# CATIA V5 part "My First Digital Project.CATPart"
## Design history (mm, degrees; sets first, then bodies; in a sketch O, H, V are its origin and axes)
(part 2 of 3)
Set37 "UDF Geometry"
  Point54 "B-L": (25.4 {= UdfFeature14.FrameThickness}, 0, 25.4 {= UdfFeature14.FrameThickness}), relative to vertex [YZ plane of UdfFeature14 | ZX plane of UdfFeature14 | XY plane of UdfFeature14], in 
  Point55 "B": (507.9492 {= `UdfFeature14.Panel Width` /2}, 0, 25.4 {= UdfFeature14.FrameThickness}), relative to vertex [YZ plane of UdfFeature14 | ZX plane of UdfFeature14 | XY plane of UdfFeature14], in 
  Point56 "B-R": (990.4984 {= `UdfFeature14.Panel Width` -UdfFeature14.FrameThickness}, 0, 25.4 {= UdfFeature14.FrameThickness}), relative to vertex [YZ plane of UdfFeature14 | ZX plane of UdfFeature14 | XY plane of UdfFeature14], in 
  Point57 "R": (990.4984 {= Point56.X}, 0, 1143 {= `UdfFeature14.Panel Height` /2}), relative to vertex [YZ plane of UdfFeature14 | ZX plane of UdfFeature14 | XY plane of UdfFeature14], in 
  Point58 "T-R": (990.4984 {= Point56.X}, 0, 2260.6 {= `UdfFeature14.Panel Height` -UdfFeature14.FrameThickness}), relative to vertex [YZ plane of UdfFeature14 | ZX plane of UdfFeature14 | XY plane of UdfFeature14], in 
  Point59 "T": (507.9492 {= Point55.X}, 0, 2260.6 {= Point58.Z}), relative to vertex [YZ plane of UdfFeature14 | ZX plane of UdfFeature14 | XY plane of UdfFeature14], in 
  Point60 "T-L": (25.4 {= Point54.X}, 0, 2260.6 {= Point58.Z}), relative to vertex [YZ plane of UdfFeature14 | ZX plane of UdfFeature14 | XY plane of UdfFeature14], in 
  Point61 "L": (25.4 {= Point54.X}, 0, 1143 {= Point57.Z}), relative to vertex [YZ plane of UdfFeature14 | ZX plane of UdfFeature14 | XY plane of UdfFeature14], in 
  Point62 "C": (507.9492 {= `UdfFeature14.Panel Width` /2}, 0, 1143 {= `UdfFeature14.Panel Height` /2}), relative to vertex [YZ plane of UdfFeature14 | ZX plane of UdfFeature14 | XY plane of UdfFeature14], in 
  Point63 "B2": (0, 0, 76.2), relative to Point55, in 
  Point64 "T2": (0, 0, -76.2), relative to Point59, in 
  Point65 "L2": (76.2, 0, 0), relative to Point61, in 
  Point66 "R2": (-76.2, 0, 0), relative to Point57, in 
  Point67 "L3": (-253.9746 {= -`UdfFeature14.Panel Width` /4}, 0, 0), relative to Point62, in 
  Point68 "R3": (253.9746 {= -Point67.X}, 0, 0), relative to Point62, in 
  Point69 "T3": (0, 0, 571.5 {= `UdfFeature14.Panel Height` /4}), relative to Point62, in 
  Point70 "B3": (0, 0, -571.5 {= - Point69.Z}), relative to Point62, in 
  LineCorner13 "Left": Elements (Point60; Point57; Point54)
  LineCorner14 "Right": Elements (Point58; Point61; Point56)
  LineCorner15 "Top": Elements (Point60; Point55; Point58)
  LineCorner16 "Bottom": Elements (Point54; Point59; Point56)
  Join6 "Left and Bottom": Elements (LineCorner13; LineCorner16)
  Join7 "Right and Bottom": Elements (LineCorner14; LineCorner16)
  LineCorner17 "Pivot H Top": Elements (Point65; Point61; Point59; Point57; Point66)
  LineCorner18 "Pivot H Bottom": Elements (Point61; Point55; Point57)
  Join8 "Pivot H": Elements (LineCorner17; LineCorner18)
  LineCorner19 "Pivot V Left": Elements (Point64; Point59; Point61; Point55; Point63)
  LineCorner20 "Pivot V Right": Elements (Point59; Point57; Point55)
  Join9 "Pivot V": Elements (LineCorner19; LineCorner20)
  Line28 "Sliding H": type PtPt, FirstPoint Point67, SecondPoint Point68
  Line29 "Sliding V": type PtPt, FirstPoint Point69, SecondPoint Point70
  Point71: (25.4 {= UdfFeature14.FrameThickness}, 0, 0), relative to Point54, in 
  Point72: (-25.4 {= -UdfFeature14.FrameThickness}, 0, 25.4 {= UdfFeature14.FrameThickness}), relative to Point56, in 
  Point73: (25.4 {= UdfFeature14.FrameThickness}, 0, -25.4 {= -UdfFeature14.FrameThickness}), relative to Point60, in 
  Point74: (-25.4 {= -UdfFeature14.FrameThickness}, 0, 0), relative to Point58, in 
  Point75: (0, 0, -25.4 {= -UdfFeature14.FrameThickness}), relative to Point58, in 
  Point76: (0, 0, 25.4 {= UdfFeature14.FrameThickness}), relative to Point54, in 
  LineCorner21 "Removable-1": Elements (Point60; Point74; Point72; Point76)
  LineCorner22 "Removable-2": Elements (Point73; Point75; Point56; Point71)
  Line30 "Removable-3": type PtPt, FirstPoint Point75, SecondPoint Point71
  Join10 "Removable": Elements (LineCorner21; LineCorner22; Line30)
  LineCorner23 "Fixed": Elements (Point60; Point58; Point56; Point54)
  DatumCurve2 "OperationSymbol"
Body24 "Opening Volume Body"
  GTCArcGeoOpnVolume5 "Opening Volume"
Set38 "IFC Triple Panel Vertical"
  Set39 "Construction Geometry"
    UdfFeature15 "Insertion Axis": UdfInputSpec1 {plane2lines}, UdfInputSpec3 Project11, UdfInputSpec4 Project12, UdfInputSpec5 Project13, UdfComponents Set44, UdfOutputs AxisSystem25
    AxisSystem20 "Insertion Axis Clone": origin (6685.672, 13208.4683, 742.95), X (-0.3932, -0.9195, 0), Y (0.9195, -0.3932, 0), Z (0, 0, 1)
    AxisSystem21 "Lining Axis": origin (6720.7034, 13193.4881, 742.95), X (-0.3932, -0.9195, 0), Y (0.9195, -0.3932, 0), Z (0, 0, 1)
    UdfFeature16 "Middle": UdfInputSpec1 {pointcoord X 0, Y 0, Z 0, RefAxis AxisSystem21}, UdfInputSpec2 {pointcoord X 1238.25 {= `UdfFeature16.Window Width` /2}, Y 0, Z 0, RefAxis AxisSystem21}, UdfInputSpec3 {pointcoord X 2476.5 {= `UdfFeature16.Window Width`}, Y 0, Z 0, RefAxis AxisSystem21}, UdfComponents Set45, UdfOutputs Point78
  Set40 "Window Panel - Left"
    AxisSystem22 "Panel Axis Left": origin (6684.0204, 13188.4559, 762), X (-0.3932, -0.9195, 0), Y (0.9195, -0.3932, 0), Z (0, 0, 1)
    Body25 "Panel"
      UdfFeature17 "IFC Window Panel": UdfInputSpec10 edge [ZX plane of AxisSystem22 | YZ plane of AxisSystem22], UdfInputSpec1 {pointcoord X 0 {= `External.Rotate Axis Offset`}, Y 0, Z 0, RefPoint vertex [YZ plane of AxisSystem22 | ZX plane of AxisSystem22 | XY plane of AxisSystem22], RefAxis AxisSystem22}, UdfInputSpec3 edge [ZX plane of AxisSystem22 | YZ plane of AxisSystem22], UdfInputSpec4 {pointcoord X 0, Y 0, Z 0 {= `External.Rotate Axis Offset`}, RefPoint vertex [YZ plane of AxisSystem22 | ZX plane of AxisSystem22 | XY plane of AxisSystem22], RefAxis AxisSystem22}, UdfComponents a sketch, UdfInputSpec6 edge [XY plane of AxisSystem22 | ZX plane of AxisSystem22], UdfInputSpec7 {pointcoord X 0 {= `External.X Translate`}, Y 0, Z 0 {= `External.Z Translate`}, RefPoint vertex [YZ plane of AxisSystem22 | ZX plane of AxisSystem22 | XY plane of AxisSystem22], RefAxis AxisSystem22}, UdfInputSpec9 edge [XY plane of AxisSystem22 | ZX plane of AxisSystem22], UdfActivity true, OperationType "FixedCasement", Open Ratio 10
  Set41 "Window Panel - Middle"
    AxisSystem23 "Panel Axis Middle": origin (6357.815, 12425.624, 762), X (-0.3932, -0.9195, 0), Y (0.9195, -0.3932, 0), Z (0, 0, 1)
    Body26 "Panel"
      UdfFeature18 "IFC Window Panel": UdfInputSpec10 edge [ZX plane of AxisSystem23 | YZ plane of AxisSystem23], UdfInputSpec1 {pointcoord X 0 {= `External.Rotate Axis Offset`}, Y 0, Z 0, RefPoint vertex [YZ plane of AxisSystem23 | ZX plane of AxisSystem23 | XY plane of AxisSystem23], RefAxis AxisSystem23}, UdfInputSpec3 edge [ZX plane of AxisSystem23 | YZ plane of AxisSystem23], UdfInputSpec4 {pointcoord X 0, Y 0, Z 0 {= `External.Rotate Axis Offset`}, RefPoint vertex [YZ plane of AxisSystem23 | ZX plane of AxisSystem23 | XY plane of AxisSystem23], RefAxis AxisSystem23}, UdfComponents a sketch, UdfInputSpec6 edge [XY plane of AxisSystem23 | ZX plane of AxisSystem23], UdfInputSpec7 {pointcoord X 0 {= `External.X Translate`}, Y 0, Z 0 {= `External.Z Translate`}, RefPoint vertex [YZ plane of AxisSystem23 | ZX plane of AxisSystem23 | XY plane of AxisSystem23], RefAxis AxisSystem23}, UdfInputSpec9 edge [XY plane of AxisSystem23 | ZX plane of AxisSystem23], OperationType "FixedCasement", Open Ratio 10
  Set42 "Window Panel - Right"
    AxisSystem24 "Panel Axis Right": origin (6031.6095, 11662.7921, 762), X (-0.3932, -0.9195, 0), Y (0.9195, -0.3932, 0), Z (0, 0, 1)
    Body27 "Panel"
      UdfFeature19 "IFC Window Panel": UdfInputSpec10 edge [ZX plane of AxisSystem24 | YZ plane of AxisSystem24], UdfInputSpec1 {pointcoord X 0 {= `External.Rotate Axis Offset`}, Y 0, Z 0, RefPoint vertex [YZ plane of AxisSystem24 | ZX plane of AxisSystem24 | XY plane of AxisSystem24], RefAxis AxisSystem24}, UdfInputSpec3 edge [ZX plane of AxisSystem24 | YZ plane of AxisSystem24], UdfInputSpec4 {pointcoord X 0, Y 0, Z 0 {= `External.Rotate Axis Offset`}, RefPoint vertex [YZ plane of AxisSystem24 | ZX plane of AxisSystem24 | XY plane of AxisSystem24], RefAxis AxisSystem24}, UdfComponents a sketch, UdfInputSpec6 edge [XY plane of AxisSystem24 | ZX plane of AxisSystem24], UdfInputSpec7 {pointcoord X 0 {= `External.X Translate`}, Y 0, Z 0 {= `External.Z Translate`}, RefPoint vertex [YZ plane of AxisSystem24 | ZX plane of AxisSystem24 | XY plane of AxisSystem24], RefAxis AxisSystem24}, UdfInputSpec9 edge [XY plane of AxisSystem24 | ZX plane of AxisSystem24], OperationType "FixedCasement", Open Ratio 10
  Set43 "Window Lining"
    Sketch14 "Opening Contour" on edge [XY plane of AxisSystem21 | ZX plane of AxisSystem21], origin (6720.7034, 13193.4881, 742.95), H (-0.3932, -0.9195, 0), V (0, 0, 1)
      line L1 (0, 0) -> (2476.5, 0)
      line L2 (2476.5, 0) -> (2476.5, 1866.9)
      line L3 (2476.5, 1866.9) -> (0, 1866.9)
      line L4 (0, 1866.9) -> (0, 0)
      length L4 = 1866.9
      length L3 = 2476.5
      horizontal: L1 H, L3 H
      vertical: L2 V, L4 V
    Body28 "Lining"
      Pad5: profile Sketch14, direction (-0.9195, 0.3932, 0), length 38.1, mirrored extent
      Pocket1: profile , through (limit type 3), opposite side through (limit type 3)
      Pocket2: profile , through (limit type 3), opposite side through (limit type 3)
      Pocket3: profile , through (limit type 3), opposite side through (limit type 3)
Set44 "Insertion Geometry"
  Plane11 "Construction Plane": type 2Lines
  Project11 "Insertion Point clone": Support Plane11
  Project12 "Insertion Line Clone": Support Plane11
  Project13 "Orientation Line Clone": Support Plane11
  Line31 "X Direction": type Normal, RefPoint Project11, RefSkin Plane11, Start 0, End 1
  AxisSystem25 "Insertion Axis": origin (6685.672, 13208.4683, 742.95), X (-0.3932, -0.9195, 0), Y (0.9195, -0.3932, 0), Z (0, 0, 1)
Set45 "UDF Geometry"
  Point77 "Left": (0, 0, 0), in AxisSystem21
  Point78 "Middle": (1238.25 {= `UdfFeature16.Window Width` /2}, 0, 0), in AxisSystem21
  Point79 "Right": (2476.5 {= `UdfFeature16.Window Width`}, 0, 0), in AxisSystem21
Set46 "UDF Geometry"
  Line32 "V Rotation Axis": type PtDir, RefPoint {point type Coord, X 0 {= `External.Rotate Axis Offset`}, Y 0, Z 0, RefPoint vertex [YZ plane of AxisSystem22 | ZX plane of AxisSystem22 | XY plane of AxisSystem22], RefAxis AxisSystem22}, Direction edge [ZX plane of AxisSystem22 | YZ plane of AxisSystem22], Start 0, End 304.8
  Line33 "H Rotation Axis": type PtDir, RefPoint {point type Coord, X 0, Y 0, Z 0 {= `External.Rotate Axis Offset`}, RefPoint vertex [YZ plane of AxisSystem22 | ZX plane of AxisSystem22 | XY plane of AxisSystem22], RefAxis AxisSystem22}, Direction edge [XY plane of AxisSystem22 | ZX plane of AxisSystem22], Start 0, End 304.8
  Point80 "Translate Point": (0 {= `External.X Translate`}, 0, 0 {= `External.Z Translate`}), relative to vertex [YZ plane of AxisSystem22 | ZX plane of AxisSystem22 | XY plane of AxisSystem22], in AxisSystem22
  Line34 "Trans X Axis": type PtDir, RefPoint Point80, Direction edge [XY plane of AxisSystem22 | ZX plane of AxisSystem22], Start 0, End 304.8
  Line35 "Trans ZAxis": type PtDir, RefPoint Point80, Direction edge [ZX plane of AxisSystem22 | YZ plane of AxisSystem22], Start 0, End 304.8
  Rotate9 "Rotate Horizontal Point": ToTransfor Point80, Axis Line33, Angle 0 {= `External.Open Angle`}
  Rotate10 "Rotate Horizontal Z Axis": ToTransfor Line35, Axis Line33, Angle 0 {= `External.Open Angle`}
  Rotate11 "Rotate Vertical Point": ToTransfor Point80, Axis Line32, Angle 0 {= `External.Open Angle`}
  Rotate12 "Rotate Vertical X Axis": ToTransfor Line34, Axis Line32, Angle 0 {= `External.Open Angle`}
  Line36 "X Direction": stored without definition
  Line37 "Z Direction": stored without definition
  Point81 "Origin": stored without definition
  Plane12: type Normal, Curve Line37, RefPoint Point81
  Line38 "Y Direction": type Angle, RefPoint Point81, Curve Line36, Support Plane12, Start 0, End 304.8, Angle 90
  AxisSystem26 "Window Open Axis": origin (6684.0204, 13188.4559, 762), X (-0.3932, -0.9195, 0), Y (0.9195, -0.3932, 0), Z (0, 0, 1)
Set47 "UDF Geometry"
  Point82 "B-L": (25.4 {= UdfFeature17.FrameThickness}, 0, 25.4 {= UdfFeature17.FrameThickness}), relative to vertex [YZ plane of UdfFeature17 | ZX plane of UdfFeature17 | XY plane of UdfFeature17], in 
  Point83 "B": (389.426 {= `UdfFeature17.Panel Width` /2}, 0, 25.4 {= UdfFeature17.FrameThickness}), relative to vertex [YZ plane of UdfFeature17 | ZX plane of UdfFeature17 | XY plane of UdfFeature17], in 
  Point84 "B-R": (753.4521 {= `UdfFeature17.Panel Width` -UdfFeature17.FrameThickness}, 0, 25.4 {= UdfFeature17.FrameThickness}), relative to vertex [YZ plane of UdfFeature17 | ZX plane of UdfFeature17 | XY plane of UdfFeature17], in 
  Point85 "R": (753.4521 {= Point84.X}, 0, 914.4 {= `UdfFeature17.Panel Height` /2}), relative to vertex [YZ plane of UdfFeature17 | ZX plane of UdfFeature17 | XY plane of UdfFeature17], in 
  Point86 "T-R": (753.4521 {= Point84.X}, 0, 1803.4 {= `UdfFeature17.Panel Height` -UdfFeature17.FrameThickness}), relative to vertex [YZ plane of UdfFeature17 | ZX plane of UdfFeature17 | XY plane of UdfFeature17], in 
  Point87 "T": (389.426 {= Point83.X}, 0, 1803.4 {= Point86.Z}), relative to vertex [YZ plane of UdfFeature17 | ZX plane of UdfFeature17 | XY plane of UdfFeature17], in 
  Point88 "T-L": (25.4 {= Point82.X}, 0, 1803.4 {= Point86.Z}), relative to vertex [YZ plane of UdfFeature17 | ZX plane of UdfFeature17 | XY plane of UdfFeature17], in 
  Point89 "L": (25.4 {= Point82.X}, 0, 914.4 {= Point85.Z}), relative to vertex [YZ plane of UdfFeature17 | ZX plane of UdfFeature17 | XY plane of UdfFeature17], in 
  Point90 "C": (389.426 {= `UdfFeature17.Panel Width` /2}, 0, 914.4 {= `UdfFeature17.Panel Height` /2}), relative to vertex [YZ plane of UdfFeature17 | ZX plane of UdfFeature17 | XY plane of UdfFeature17], in 
  Point91 "B2": (0, 0, 76.2), relative to Point83, in 
  Point92 "T2": (0, 0, -76.2), relative to Point87, in 
  Point93 "L2": (76.2, 0, 0), relative to Point89, in 
  Point94 "R2": (-76.2, 0, 0), relative to Point85, in 
  Point95 "L3": (-194.713 {= -`UdfFeature17.Panel Width` /4}, 0, 0), relative to Point90, in 
  Point96 "R3": (194.713 {= -Point95.X}, 0, 0), relative to Point90, in 
  Point97 "T3": (0, 0, 457.2 {= `UdfFeature17.Panel Height` /4}), relative to Point90, in 
  Point98 "B3": (0, 0, -457.2 {= - Point97.Z}), relative to Point90, in 
  LineCorner24 "Left": Elements (Point88; Point85; Point82)
  LineCorner25 "Right": Elements (Point86; Point89; Point84)
  LineCorner26 "Top": Elements (Point88; Point83; Point86)
  LineCorner27 "Bottom": Elements (Point82; Point87; Point84)
  Join11 "Left and Bottom": Elements (LineCorner24; LineCorner27)
  Join12 "Right and Bottom": Elements (LineCorner25; LineCorner27)
  LineCorner28 "Pivot H Top": Elements (Point93; Point89; Point87; Point85; Point94)
  LineCorner29 "Pivot H Bottom": Elements (Point89; Point83; Point85)
  Join13 "Pivot H": Elements (LineCorner28; LineCorner29)
  LineCorner30 "Pivot V Left": Elements (Point92; Point87; Point89; Point83; Point91)
  LineCorner31 "Pivot V Right": Elements (Point87; Point85; Point83)
  Join14 "Pivot V": Elements (LineCorner30; LineCorner31)
  Line39 "Sliding H": type PtPt, FirstPoint Point95, SecondPoint Point96
  Line40 "Sliding V": type PtPt, FirstPoint Point97, SecondPoint Point98
  Point99: (25.4 {= UdfFeature17.FrameThickness}, 0, 0), relative to Point82, in 
  Point100: (-25.4 {= -UdfFeature17.FrameThickness}, 0, 25.4 {= UdfFeature17.FrameThickness}), relative to Point84, in 
  Point101: (25.4 {= UdfFeature17.FrameThickness}, 0, -25.4 {= -UdfFeature17.FrameThickness}), relative to Point88, in 
  Point102: (-25.4 {= -UdfFeature17.FrameThickness}, 0, 0), relative to Point86, in 
  Point103: (0, 0, -25.4 {= -UdfFeature17.FrameThickness}), relative to Point86, in 
  Point104: (0, 0, 25.4 {= UdfFeature17.FrameThickness}), relative to Point82, in 
  LineCorner32 "Removable-1": Elements (Point88; Point102; Point100; Point104)
  LineCorner33 "Removable-2": Elements (Point101; Point103; Point84; Point99)
  Line41 "Removable-3": type PtPt, FirstPoint Point103, SecondPoint Point99
  Join15 "Removable": Elements (LineCorner32; LineCorner33; Line41)
  LineCorner34 "Fixed": Elements (Point88; Point86; Point84; Point82)
  DatumCurve3 "OperationSymbol"
Set48 "UDF Geometry"
  Line42 "V Rotation Axis": type PtDir, RefPoint {point type Coord, X 0 {= `External.Rotate Axis Offset`}, Y 0, Z 0, RefPoint vertex [YZ plane of AxisSystem23 | ZX plane of AxisSystem23 | XY plane of AxisSystem23], RefAxis AxisSystem23}, Direction edge [ZX plane of AxisSystem23 | YZ plane of AxisSystem23], Start 0, End 304.8
  Line43 "H Rotation Axis": type PtDir, RefPoint {point type Coord, X 0, Y 0, Z 0 {= `External.Rotate Axis Offset`}, RefPoint vertex [YZ plane of AxisSystem23 | ZX plane of AxisSystem23 | XY plane of AxisSystem23], RefAxis AxisSystem23}, Direction edge [XY plane of AxisSystem23 | ZX plane of AxisSystem23], Start 0, End 304.8
  Point105 "Translate Point": (0 {= `External.X Translate`}, 0, 0 {= `External.Z Translate`}), relative to vertex [YZ plane of AxisSystem23 | ZX plane of AxisSystem23 | XY plane of AxisSystem23], in AxisSystem23
  Line44 "Trans X Axis": type PtDir, RefPoint Point105, Direction edge [XY plane of AxisSystem23 | ZX plane of AxisSystem23], Start 0, End 304.8
  Line45 "Trans ZAxis": type PtDir, RefPoint Point105, Direction edge [ZX plane of AxisSystem23 | YZ plane of AxisSystem23], Start 0, End 304.8
  Rotate13 "Rotate Horizontal Point": ToTransfor Point105, Axis Line43, Angle 0 {= `External.Open Angle`}
  Rotate14 "Rotate Horizontal Z Axis": ToTransfor Line45, Axis Line43, Angle 0 {= `External.Open Angle`}
  Rotate15 "Rotate Vertical Point": ToTransfor Point105, Axis Line42, Angle 0 {= `External.Open Angle`}
  Rotate16 "Rotate Vertical X Axis": ToTransfor Line44, Axis Line42, Angle 0 {= `External.Open Angle`}
  Line46 "X Direction": stored without definition
  Line47 "Z Direction": stored without definition
  Point106 "Origin": stored without definition
  Plane13: type Normal, Curve Line47, RefPoint Point106
  Line48 "Y Direction": type Angle, RefPoint Point106, Curve Line46, Support Plane13, Start 0, End 304.8, Angle 90
  AxisSystem27 "Window Open Axis": origin (6357.815, 12425.624, 762), X (-0.3932, -0.9195, 0), Y (0.9195, -0.3932, 0), Z (0, 0, 1)
Set49 "UDF Geometry"
  Point107 "B-L": (25.4 {= UdfFeature18.FrameThickness}, 0, 25.4 {= UdfFeature18.FrameThickness}), relative to vertex [YZ plane of UdfFeature18 | ZX plane of UdfFeature18 | XY plane of UdfFeature18], in 
  Point108 "B": (389.426 {= `UdfFeature18.Panel Width` /2}, 0, 25.4 {= UdfFeature18.FrameThickness}), relative to vertex [YZ plane of UdfFeature18 | ZX plane of UdfFeature18 | XY plane of UdfFeature18], in 
  Point109 "B-R": (753.4521 {= `UdfFeature18.Panel Width` -UdfFeature18.FrameThickness}, 0, 25.4 {= UdfFeature18.FrameThickness}), relative to vertex [YZ plane of UdfFeature18 | ZX plane of UdfFeature18 | XY plane of UdfFeature18], in 
  Point110 "R": (753.4521 {= Point109.X}, 0, 914.4 {= `UdfFeature18.Panel Height` /2}), relative to vertex [YZ plane of UdfFeature18 | ZX plane of UdfFeature18 | XY plane of UdfFeature18], in 
  Point111 "T-R": (753.4521 {= Point109.X}, 0, 1803.4 {= `UdfFeature18.Panel Height` -UdfFeature18.FrameThickness}), relative to vertex [YZ plane of UdfFeature18 | ZX plane of UdfFeature18 | XY plane of UdfFeature18], in 
  Point112 "T": (389.426 {= Point108.X}, 0, 1803.4 {= Point111.Z}), relative to vertex [YZ plane of UdfFeature18 | ZX plane of UdfFeature18 | XY plane of UdfFeature18], in 
  Point113 "T-L": (25.4 {= Point107.X}, 0, 1803.4 {= Point111.Z}), relative to vertex [YZ plane of UdfFeature18 | ZX plane of UdfFeature18 | XY plane of UdfFeature18], in 
  Point114 "L": (25.4 {= Point107.X}, 0, 914.4 {= Point110.Z}), relative to vertex [YZ plane of UdfFeature18 | ZX plane of UdfFeature18 | XY plane of UdfFeature18], in 
  Point115 "C": (389.426 {= `UdfFeature18.Panel Width` /2}, 0, 914.4 {= `UdfFeature18.Panel Height` /2}), relative to vertex [YZ plane of UdfFeature18 | ZX plane of UdfFeature18 | XY plane of UdfFeature18], in 
  Point116 "B2": (0, 0, 76.2), relative to Point108, in 
  Point117 "T2": (0, 0, -76.2), relative to Point112, in 
  Point118 "L2": (76.2, 0, 0), relative to Point114, in 
  Point119 "R2": (-76.2, 0, 0), relative to Point110, in 
  Point120 "L3": (-194.713 {= -`UdfFeature18.Panel Width` /4}, 0, 0), relative to Point115, in 
  Point121 "R3": (194.713 {= -Point120.X}, 0, 0), relative to Point115, in 
  Point122 "T3": (0, 0, 457.2 {= `UdfFeature18.Panel Height` /4}), relative to Point115, in 
  Point123 "B3": (0, 0, -457.2 {= - Point122.Z}), relative to Point115, in 
  LineCorner35 "Left": Elements (Point113; Point110; Point107)
  LineCorner36 "Right": Elements (Point111; Point114; Point109)
  LineCorner37 "Top": Elements (Point113; Point108; Point111)
  LineCorner38 "Bottom": Elements (Point107; Point112; Point109)
  Join16 "Left and Bottom": Elements (LineCorner35; LineCorner38)
  Join17 "Right and Bottom": Elements (LineCorner36; LineCorner38)
  LineCorner39 "Pivot H Top": Elements (Point118; Point114; Point112; Point110; Point119)
  LineCorner40 "Pivot H Bottom": Elements (Point114; Point108; Point110)
  Join18 "Pivot H": Elements (LineCorner39; LineCorner40)
  LineCorner41 "Pivot V Left": Elements (Point117; Point112; Point114; Point108; Point116)
  LineCorner42 "Pivot V Right": Elements (Point112; Point110; Point108)
  Join19 "Pivot V": Elements (LineCorner41; LineCorner42)
  Line49 "Sliding H": type PtPt, FirstPoint Point120, SecondPoint Point121
  Line50 "Sliding V": type PtPt, FirstPoint Point122, SecondPoint Point123
  Point124: (25.4 {= UdfFeature18.FrameThickness}, 0, 0), relative to Point107, in 
  Point125: (-25.4 {= -UdfFeature18.FrameThickness}, 0, 25.4 {= UdfFeature18.FrameThickness}), relative to Point109, in 
  Point126: (25.4 {= UdfFeature18.FrameThickness}, 0, -25.4 {= -UdfFeature18.FrameThickness}), relative to Point113, in 
  Point127: (-25.4 {= -UdfFeature18.FrameThickness}, 0, 0), relative to Point111, in 
  Point128: (0, 0, -25.4 {= -UdfFeature18.FrameThickness}), relative to Point111, in 
  Point129: (0, 0, 25.4 {= UdfFeature18.FrameThickness}), relative to Point107, in 
  LineCorner43 "Removable-1": Elements (Point113; Point127; Point125; Point129)
  LineCorner44 "Removable-2": Elements (Point126; Point128; Point109; Point124)
  Line51 "Removable-3": type PtPt, FirstPoint Point128, SecondPoint Point124
  Join20 "Removable": Elements (LineCorner43; LineCorner44; Line51)
  LineCorner45 "Fixed": Elements (Point113; Point111; Point109; Point107)
  DatumCurve4 "OperationSymbol"
Set50 "UDF Geometry"
  Line52 "V Rotation Axis": type PtDir, RefPoint {point type Coord, X 0 {= `External.Rotate Axis Offset`}, Y 0, Z 0, RefPoint vertex [YZ plane of AxisSystem24 | ZX plane of AxisSystem24 | XY plane of AxisSystem24], RefAxis AxisSystem24}, Direction edge [ZX plane of AxisSystem24 | YZ plane of AxisSystem24], Start 0, End 304.8
  Line53 "H Rotation Axis": type PtDir, RefPoint {point type Coord, X 0, Y 0, Z 0 {= `External.Rotate Axis Offset`}, RefPoint vertex [YZ plane of AxisSystem24 | ZX plane of AxisSystem24 | XY plane of AxisSystem24], RefAxis AxisSystem24}, Direction edge [XY plane of AxisSystem24 | ZX plane of AxisSystem24], Start 0, End 304.8
  Point130 "Translate Point": (0 {= `External.X Translate`}, 0, 0 {= `External.Z Translate`}), relative to vertex [YZ plane of AxisSystem24 | ZX plane of AxisSystem24 | XY plane of AxisSystem24], in AxisSystem24
  Line54 "Trans X Axis": type PtDir, RefPoint Point130, Direction edge [XY plane of AxisSystem24 | ZX plane of AxisSystem24], Start 0, End 304.8
  Line55 "Trans ZAxis": type PtDir, RefPoint Point130, Direction edge [ZX plane of AxisSystem24 | YZ plane of AxisSystem24], Start 0, End 304.8
  Rotate17 "Rotate Horizontal Point": ToTransfor Point130, Axis Line53, Angle 0 {= `External.Open Angle`}
  Rotate18 "Rotate Horizontal Z Axis": ToTransfor Line55, Axis Line53, Angle 0 {= `External.Open Angle`}
  Rotate19 "Rotate Vertical Point": ToTransfor Point130, Axis Line52, Angle 0 {= `External.Open Angle`}
  Rotate20 "Rotate Vertical X Axis": ToTransfor Line54, Axis Line52, Angle 0 {= `External.Open Angle`}
  Line56 "X Direction": stored without definition
  Line57 "Z Direction": stored without definition
  Point131 "Origin": stored without definition
  Plane14: type Normal, Curve Line57, RefPoint Point131
  Line58 "Y Direction": type Angle, RefPoint Point131, Curve Line56, Support Plane14, Start 0, End 304.8, Angle 90
  AxisSystem28 "Window Open Axis": origin (6031.6095, 11662.7921, 762), X (-0.3932, -0.9195, 0), Y (0.9195, -0.3932, 0), Z (0, 0, 1)
Set51 "UDF Geometry"
  Point132 "B-L": (25.4 {= UdfFeature19.FrameThickness}, 0, 25.4 {= UdfFeature19.FrameThickness}), relative to vertex [YZ plane of UdfFeature19 | ZX plane of UdfFeature19 | XY plane of UdfFeature19], in 
  Point133 "B": (389.5479 {= `UdfFeature19.Panel Width` /2}, 0, 25.4 {= UdfFeature19.FrameThickness}), relative to vertex [YZ plane of UdfFeature19 | ZX plane of UdfFeature19 | XY plane of UdfFeature19], in 
  Point134 "B-R": (753.6959 {= `UdfFeature19.Panel Width` -UdfFeature19.FrameThickness}, 0, 25.4 {= UdfFeature19.FrameThickness}), relative to vertex [YZ plane of UdfFeature19 | ZX plane of UdfFeature19 | XY plane of UdfFeature19], in 
  Point135 "R": (753.6959 {= Point134.X}, 0, 914.4 {= `UdfFeature19.Panel Height` /2}), relative to vertex [YZ plane of UdfFeature19 | ZX plane of UdfFeature19 | XY plane of UdfFeature19], in 
  Point136 "T-R": (753.6959 {= Point134.X}, 0, 1803.4 {= `UdfFeature19.Panel Height` -UdfFeature19.FrameThickness}), relative to vertex [YZ plane of UdfFeature19 | ZX plane of UdfFeature19 | XY plane of UdfFeature19], in 
  Point137 "T": (389.5479 {= Point133.X}, 0, 1803.4 {= Point136.Z}), relative to vertex [YZ plane of UdfFeature19 | ZX plane of UdfFeature19 | XY plane of UdfFeature19], in 
  Point138 "T-L": (25.4 {= Point132.X}, 0, 1803.4 {= Point136.Z}), relative to vertex [YZ plane of UdfFeature19 | ZX plane of UdfFeature19 | XY plane of UdfFeature19], in 
  Point139 "L": (25.4 {= Point132.X}, 0, 914.4 {= Point135.Z}), relative to vertex [YZ plane of UdfFeature19 | ZX plane of UdfFeature19 | XY plane of UdfFeature19], in 
  Point140 "C": (389.5479 {= `UdfFeature19.Panel Width` /2}, 0, 914.4 {= `UdfFeature19.Panel Height` /2}), relative to vertex [YZ plane of UdfFeature19 | ZX plane of UdfFeature19 | XY plane of UdfFeature19], in 
  Point141 "B2": (0, 0, 76.2), relative to Point133, in 
  Point142 "T2": (0, 0, -76.2), relative to Point137, in 
  Point143 "L2": (76.2, 0, 0), relative to Point139, in 
  Point144 "R2": (-76.2, 0, 0), relative to Point135, in 
  Point145 "L3": (-194.774 {= -`UdfFeature19.Panel Width` /4}, 0, 0), relative to Point140, in 
  Point146 "R3": (194.774 {= -Point145.X}, 0, 0), relative to Point140, in 
  Point147 "T3": (0, 0, 457.2 {= `UdfFeature19.Panel Height` /4}), relative to Point140, in 
  Point148 "B3": (0, 0, -457.2 {= - Point147.Z}), relative to Point140, in 
  LineCorner46 "Left": Elements (Point138; Point135; Point132)
  LineCorner47 "Right": Elements (Point136; Point139; Point134)
  LineCorner48 "Top": Elements (Point138; Point133; Point136)
  LineCorner49 "Bottom": Elements (Point132; Point137; Point134)
  Join21 "Left and Bottom": Elements (LineCorner46; LineCorner49)
  Join22 "Right and Bottom": Elements (LineCorner47; LineCorner49)
  LineCorner50 "Pivot H Top": Elements (Point143; Point139; Point137; Point135; Point144)
  LineCorner51 "Pivot H Bottom": Elements (Point139; Point133; Point135)
  Join23 "Pivot H": Elements (LineCorner50; LineCorner51)
  LineCorner52 "Pivot V Left": Elements (Point142; Point137; Point139; Point133; Point141)
  LineCorner53 "Pivot V Right": Elements (Point137; Point135; Point133)
  Join24 "Pivot V": Elements (LineCorner52; LineCorner53)
  Line59 "Sliding H": type PtPt, FirstPoint Point145, SecondPoint Point146
  Line60 "Sliding V": type PtPt, FirstPoint Point147, SecondPoint Point148
  Point149: (25.4 {= UdfFeature19.FrameThickness}, 0, 0), relative to Point132, in 
  Point150: (-25.4 {= -UdfFeature19.FrameThickness}, 0, 25.4 {= UdfFeature19.FrameThickness}), relative to Point134, in 
  Point151: (25.4 {= UdfFeature19.FrameThickness}, 0, -25.4 {= -UdfFeature19.FrameThickness}), relative to Point138, in 
  Point152: (-25.4 {= -UdfFeature19.FrameThickness}, 0, 0), relative to Point136, in 
  Point153: (0, 0, -25.4 {= -UdfFeature19.FrameThickness}), relative to Point136, in 
  Point154: (0, 0, 25.4 {= UdfFeature19.FrameThickness}), relative to Point132, in 
  LineCorner54 "Removable-1": Elements (Point138; Point152; Point150; Point154)
  LineCorner55 "Removable-2": Elements (Point151; Point153; Point134; Point149)
  Line61 "Removable-3": type PtPt, FirstPoint Point153, SecondPoint Point149
  Join25 "Removable": Elements (LineCorner54; LineCorner55; Line61)
  LineCorner56 "Fixed": Elements (Point138; Point136; Point134; Point132)
  DatumCurve5 "OperationSymbol"
Body29 "Opening Volume Body"
  GTCArcGeoOpnVolume6 "Opening Volume"
Set52 "IFC Single Panel"
  Set53 "Construction Geometry"
    UdfFeature20 "Insertion Axis": UdfInputSpec1 {plane2lines}, UdfInputSpec3 Project14, UdfInputSpec4 Project15, UdfInputSpec5 Project16, UdfComponents Set56, UdfOutputs AxisSystem32
    AxisSystem29 "Insertion Axis Clone": origin (13730.5463, 7614.1343, 133.35), X (0.4345, 0.9007, 0), Y (-0.9007, 0.4345, 0), Z (0, 0, 1)
    AxisSystem30 "Lining Axis": origin (13696.2308, 7630.689, 133.35), X (0.4345, 0.9007, 0), Y (-0.9007, 0.4345, 0), Z (0, 0, 1)
    AxisSystem31 "Panel Axis": origin (13733.1044, 7634.0512, 152.4), X (0.4345, 0.9007, 0), Y (-0.9007, 0.4345, 0), Z (0, 0, 1)
    UdfFeature21 "Middle": UdfInputSpec1 {pointcoord X 0, Y 0, Z 0, RefAxis AxisSystem30}, UdfInputSpec2 {pointcoord X 526.9992 {= `UdfFeature21.Window Width` /2}, Y 0, Z 0, RefAxis AxisSystem30}, UdfInputSpec3 {pointcoord X 1053.9984 {= `UdfFeature21.Window Width`}, Y 0, Z 0, RefAxis AxisSystem30}, UdfComponents Set57, UdfOutputs Point156
  Set54 "Window Lining"
    Sketch15 "Opening Contour" on edge [XY plane of AxisSystem30 | ZX plane of AxisSystem30], origin (13696.2308, 7630.689, 133.35), H (0.4345, 0.9007, 0), V (0, 0, 1)
      line L1 (0, 0) -> (1053.9984, 0)
      line L2 (1053.9984, 0) -> (1053.9984, 2324.1)
      line L3 (1053.9984, 2324.1) -> (0, 2324.1)
      line L4 (0, 2324.1) -> (0, 0)
      length L4 = 2324.1
      length L3 = 1053.9984
      horizontal: L1 H, L3 H
      vertical: L2 V, L4 V
    Body30 "Lining"
      Pad6: profile Sketch15, direction (0.9007, -0.4345, 0), length 38.1, mirrored extent, thin wall 19.05
  Set55 "Window Panel"
    Body31 "Panel"
      UdfFeature22 "IFC Window Panel": UdfInputSpec10 edge [ZX plane of AxisSystem31 | YZ plane of AxisSystem31], UdfInputSpec1 {pointcoord X 1015.8984 {= `External.Rotate Axis Offset`}, Y 0, Z 0, RefPoint vertex [YZ plane of AxisSystem31 | ZX plane of AxisSystem31 | XY plane of AxisSystem31], RefAxis AxisSystem31}, UdfInputSpec3 edge [ZX plane of AxisSystem31 | YZ plane of AxisSystem31], UdfInputSpec4 {pointcoord X 0, Y 0, Z 1015.8984 {= `External.Rotate Axis Offset`}, RefPoint vertex [YZ plane of AxisSystem31 | ZX plane of AxisSystem31 | XY plane of AxisSystem31], RefAxis AxisSystem31}, UdfComponents a sketch, UdfInputSpec6 edge [XY plane of AxisSystem31 | ZX plane of AxisSystem31], UdfInputSpec7 {pointcoord X 0 {= `External.X Translate`}, Y 0, Z 0 {= `External.Z Translate`}, RefPoint vertex [YZ plane of AxisSystem31 | ZX plane of AxisSystem31 | XY plane of AxisSystem31], RefAxis AxisSystem31}, UdfInputSpec9 edge [XY plane of AxisSystem31 | ZX plane of AxisSystem31], OperationType "SideHungRightHand", Open Ratio 0
Set56 "Insertion Geometry"
  Plane15 "Construction Plane": type 2Lines
  Project14 "Insertion Point clone": Support Plane15
  Project15 "Insertion Line Clone": Support Plane15
  Project16 "Orientation Line Clone": Support Plane15
  Line62 "X Direction": type Normal, RefPoint Project14, RefSkin Plane15, Start 0, End 1
  AxisSystem32 "Insertion Axis": origin (13730.5463, 7614.1343, 133.35), X (0.4345, 0.9007, 0), Y (-0.9007, 0.4345, 0), Z (0, 0, 1)
Set57 "UDF Geometry"
  Point155 "Left": (0, 0, 0), in AxisSystem30
  Point156 "Middle": (526.9992 {= `UdfFeature21.Window Width` /2}, 0, 0), in AxisSystem30
  Point157 "Right": (1053.9984 {= `UdfFeature21.Window Width`}, 0, 0), in AxisSystem30
Set58 "UDF Geometry"
  Line63 "V Rotation Axis": type PtDir, RefPoint {point type Coord, X 1015.8984 {= `External.Rotate Axis Offset`}, Y 0, Z 0, RefPoint vertex [YZ plane of AxisSystem31 | ZX plane of AxisSystem31 | XY plane of AxisSystem31], RefAxis AxisSystem31}, Direction edge [ZX plane of AxisSystem31 | YZ plane of AxisSystem31], Start 0, End 304.8
  Line64 "H Rotation Axis": type PtDir, RefPoint {point type Coord, X 0, Y 0, Z 1015.8984 {= `External.Rotate Axis Offset`}, RefPoint vertex [YZ plane of AxisSystem31 | ZX plane of AxisSystem31 | XY plane of AxisSystem31], RefAxis AxisSystem31}, Direction edge [XY plane of AxisSystem31 | ZX plane of AxisSystem31], Start 0, End 304.8
  Point158 "Translate Point": (0 {= `External.X Translate`}, 0, 0 {= `External.Z Translate`}), relative to vertex [YZ plane of AxisSystem31 | ZX plane of AxisSystem31 | XY plane of AxisSystem31], in AxisSystem31
  Line65 "Trans X Axis": type PtDir, RefPoint Point158, Direction edge [XY plane of AxisSystem31 | ZX plane of AxisSystem31], Start 0, End 304.8
  Line66 "Trans ZAxis": type PtDir, RefPoint Point158, Direction edge [ZX plane of AxisSystem31 | YZ plane of AxisSystem31], Start 0, End 304.8
  Rotate21 "Rotate Horizontal Point": ToTransfor Point158, Axis Line64, Angle 0 {= `External.Open Angle`}
  Rotate22 "Rotate Horizontal Z Axis": ToTransfor Line66, Axis Line64, Angle 0 {= `External.Open Angle`}
  Rotate23 "Rotate Vertical Point": ToTransfor Point158, Axis Line63, Angle 0 {= `External.Open Angle`}
  Rotate24 "Rotate Vertical X Axis": ToTransfor Line65, Axis Line63, Angle 0 {= `External.Open Angle`}
  Line67 "X Direction": stored without definition
  Line68 "Z Direction": stored without definition
  Point159 "Origin": stored without definition
  Plane16: type Normal, Curve Line68, RefPoint Point159
  Line69 "Y Direction": type Angle, RefPoint Point159, Curve Line67, Support Plane16, Start 0, End 304.8, Angle 90
  AxisSystem33 "Window Open Axis": origin (13733.1044, 7634.0512, 152.4), X (0.4345, 0.9007, 0), Y (-0.9007, 0.4345, 0), Z (0, 0, 1)
Set59 "UDF Geometry"
  Point160 "B-L": (25.4 {= UdfFeature22.FrameThickness}, 0, 25.4 {= UdfFeature22.FrameThickness}), relative to vertex [YZ plane of UdfFeature22 | ZX plane of UdfFeature22 | XY plane of UdfFeature22], in 
  Point161 "B": (507.9492 {= `UdfFeature22.Panel Width` /2}, 0, 25.4 {= UdfFeature22.FrameThickness}), relative to vertex [YZ plane of UdfFeature22 | ZX plane of UdfFeature22 | XY plane of UdfFeature22], in 
  Point162 "B-R": (990.4984 {= `UdfFeature22.Panel Width` -UdfFeature22.FrameThickness}, 0, 25.4 {= UdfFeature22.FrameThickness}), relative to vertex [YZ plane of UdfFeature22 | ZX plane of UdfFeature22 | XY plane of UdfFeature22], in 
  Point163 "R": (990.4984 {= Point162.X}, 0, 1143 {= `UdfFeature22.Panel Height` /2}), relative to vertex [YZ plane of UdfFeature22 | ZX plane of UdfFeature22 | XY plane of UdfFeature22], in 
  Point164 "T-R": (990.4984 {= Point162.X}, 0, 2260.6 {= `UdfFeature22.Panel Height` -UdfFeature22.FrameThickness}), relative to vertex [YZ plane of UdfFeature22 | ZX plane of UdfFeature22 | XY plane of UdfFeature22], in 
  Point165 "T": (507.9492 {= Point161.X}, 0, 2260.6 {= Point164.Z}), relative to vertex [YZ plane of UdfFeature22 | ZX plane of UdfFeature22 | XY plane of UdfFeature22], in 
  Point166 "T-L": (25.4 {= Point160.X}, 0, 2260.6 {= Point164.Z}), relative to vertex [YZ plane of UdfFeature22 | ZX plane of UdfFeature22 | XY plane of UdfFeature22], in 
  Point167 "L": (25.4 {= Point160.X}, 0, 1143 {= Point163.Z}), relative to vertex [YZ plane of UdfFeature22 | ZX plane of UdfFeature22 | XY plane of UdfFeature22], in 
  Point168 "C": (507.9492 {= `UdfFeature22.Panel Width` /2}, 0, 1143 {= `UdfFeature22.Panel Height` /2}), relative to vertex [YZ plane of UdfFeature22 | ZX plane of UdfFeature22 | XY plane of UdfFeature22], in 
  Point169 "B2": (0, 0, 76.2), relative to Point161, in 
  Point170 "T2": (0, 0, -76.2), relative to Point165, in 
  Point171 "L2": (76.2, 0, 0), relative to Point167, in 
  Point172 "R2": (-76.2, 0, 0), relative to Point163, in 
  Point173 "L3": (-253.9746 {= -`UdfFeature22.Panel Width` /4}, 0, 0), relative to Point168, in 
  Point174 "R3": (253.9746 {= -Point173.X}, 0, 0), relative to Point168, in 
  Point175 "T3": (0, 0, 571.5 {= `UdfFeature22.Panel Height` /4}), relative to Point168, in 
  Point176 "B3": (0, 0, -571.5 {= - Point175.Z}), relative to Point168, in 
  LineCorner57 "Left": Elements (Point166; Point163; Point160)
  LineCorner58 "Right": Elements (Point164; Point167; Point162)
  LineCorner59 "Top": Elements (Point166; Point161; Point164)
  LineCorner60 "Bottom": Elements (Point160; Point165; Point162)
  Join26 "Left and Bottom": Elements (LineCorner57; LineCorner60)
  Join27 "Right and Bottom": Elements (LineCorner58; LineCorner60)
  LineCorner61 "Pivot H Top": Elements (Point171; Point167; Point165; Point163; Point172)
  LineCorner62 "Pivot H Bottom": Elements (Point167; Point161; Point163)
  Join28 "Pivot H": Elements (LineCorner61; LineCorner62)
  LineCorner63 "Pivot V Left": Elements (Point170; Point165; Point167; Point161; Point169)
  LineCorner64 "Pivot V Right": Elements (Point165; Point163; Point161)
  Join29 "Pivot V": Elements (LineCorner63; LineCorner64)
  Line70 "Sliding H": type PtPt, FirstPoint Point173, SecondPoint Point174
  Line71 "Sliding V": type PtPt, FirstPoint Point175, SecondPoint Point176
  Point177: (25.4 {= UdfFeature22.FrameThickness}, 0, 0), relative to Point160, in 
  Point178: (-25.4 {= -UdfFeature22.FrameThickness}, 0, 25.4 {= UdfFeature22.FrameThickness}), relative to Point162, in 
  Point179: (25.4 {= UdfFeature22.FrameThickness}, 0, -25.4 {= -UdfFeature22.FrameThickness}), relative to Point166, in 
  Point180: (-25.4 {= -UdfFeature22.FrameThickness}, 0, 0), relative to Point164, in 
  Point181: (0, 0, -25.4 {= -UdfFeature22.FrameThickness}), relative to Point164, in 
  Point182: (0, 0, 25.4 {= UdfFeature22.FrameThickness}), relative to Point160, in 
  LineCorner65 "Removable-1": Elements (Point166; Point180; Point178; Point182)
  LineCorner66 "Removable-2": Elements (Point179; Point181; Point162; Point177)
  Line72 "Removable-3": type PtPt, FirstPoint Point181, SecondPoint Point177
  Join30 "Removable": Elements (LineCorner65; LineCorner66; Line72)
  LineCorner67 "Fixed": Elements (Point166; Point164; Point162; Point160)
  DatumCurve6 "OperationSymbol"
Body32 "Opening Volume Body"
  GTCArcGeoOpnVolume7 "Opening Volume"
Set60 "IFC Single Panel"
  Set61 "Construction Geometry"
    UdfFeature23 "Insertion Axis": UdfInputSpec1 {plane2lines}, UdfInputSpec3 Project17, UdfInputSpec4 Project18, UdfInputSpec5 Project19, UdfComponents Set64, UdfOutputs AxisSystem37
    AxisSystem34 "Insertion Axis Clone": origin (14253.4944, 8715.4862, 133.35), X (0.3511, 0.9364, 0), Y (-0.9364, 0.3511, 0), Z (0, 0, 1)
    AxisSystem35 "Lining Axis": origin (14217.8192, 8728.8612, 133.35), X (0.3511, 0.9364, 0), Y (-0.9364, 0.3511, 0), Z (0, 0, 1)
    AxisSystem36 "Panel Axis": origin (14254.236, 8735.553, 152.4), X (0.3511, 0.9364, 0), Y (-0.9364, 0.3511, 0), Z (0, 0, 1)
    UdfFeature24 "Middle": UdfInputSpec1 {pointcoord X 0, Y 0, Z 0, RefAxis AxisSystem35}, UdfInputSpec2 {pointcoord X 526.9992 {= `UdfFeature24.Window Width` /2}, Y 0, Z 0, RefAxis AxisSystem35}, UdfInputSpec3 {pointcoord X 1053.9984 {= `UdfFeature24.Window Width`}, Y 0, Z 0, RefAxis AxisSystem35}, UdfComponents Set65, UdfOutputs Point184
  Set62 "Window Lining"
    Sketch16 "Opening Contour" on edge [XY plane of AxisSystem35 | ZX plane of AxisSystem35], origin (14217.8192, 8728.8612, 133.35), H (0.3511, 0.9364, 0), V (0, 0, 1)
      line L1 (0, 0) -> (1053.9984, 0)
      line L2 (1053.9984, 0) -> (1053.9984, 2324.1)
      line L3 (1053.9984, 2324.1) -> (0, 2324.1)
      line L4 (0, 2324.1) -> (0, 0)
      length L4 = 2324.1
      length L3 = 1053.9984
      horizontal: L1 H, L3 H
      vertical: L2 V, L4 V
    Body33 "Lining"
      Pad7: profile Sketch16, direction (0.9364, -0.3511, 0), length 38.1, mirrored extent, thin wall 19.05
  Set63 "Window Panel"
    Body34 "Panel"
      UdfFeature25 "IFC Window Panel": UdfInputSpec10 edge [ZX plane of AxisSystem36 | YZ plane of AxisSystem36], UdfInputSpec1 {pointcoord X 1015.8984 {= `External.Rotate Axis Offset`}, Y 0, Z 0, RefPoint vertex [YZ plane of AxisSystem36 | ZX plane of AxisSystem36 | XY plane of AxisSystem36], RefAxis AxisSystem36}, UdfInputSpec3 edge [ZX plane of AxisSystem36 | YZ plane of AxisSystem36], UdfInputSpec4 {pointcoord X 0, Y 0, Z 1015.8984 {= `External.Rotate Axis Offset`}, RefPoint vertex [YZ plane of AxisSystem36 | ZX plane of AxisSystem36 | XY plane of AxisSystem36], RefAxis AxisSystem36}, UdfComponents a sketch, UdfInputSpec6 edge [XY plane of AxisSystem36 | ZX plane of AxisSystem36], UdfInputSpec7 {pointcoord X 0 {= `External.X Translate`}, Y 0, Z 0 {= `External.Z Translate`}, RefPoint vertex [YZ plane of AxisSystem36 | ZX plane of AxisSystem36 | XY plane of AxisSystem36], RefAxis AxisSystem36}, UdfInputSpec9 edge [XY plane of AxisSystem36 | ZX plane of AxisSystem36], OperationType "SideHungRightHand", Open Ratio 0
Set64 "Insertion Geometry"
  Plane17 "Construction Plane": type 2Lines
  Project17 "Insertion Point clone": Support Plane17
  Project18 "Insertion Line Clone": Support Plane17
  Project19 "Orientation Line Clone": Support Plane17
  Line73 "X Direction": type Normal, RefPoint Project17, RefSkin Plane17, Start 0, End 1
  AxisSystem37 "Insertion Axis": origin (14253.4944, 8715.4862, 133.35), X (0.3511, 0.9364, 0), Y (-0.9364, 0.3511, 0), Z (0, 0, 1)
Set65 "UDF Geometry"
  Point183 "Left": (0, 0, 0), in AxisSystem35
  Point184 "Middle": (526.9992 {= `UdfFeature24.Window Width` /2}, 0, 0), in AxisSystem35
  Point185 "Right": (1053.9984 {= `UdfFeature24.Window Width`}, 0, 0), in AxisSystem35
Set66 "UDF Geometry"
  Line74 "V Rotation Axis": type PtDir, RefPoint {point type Coord, X 1015.8984 {= `External.Rotate Axis Offset`}, Y 0, Z 0, RefPoint vertex [YZ plane of AxisSystem36 | ZX plane of AxisSystem36 | XY plane of AxisSystem36], RefAxis AxisSystem36}, Direction edge [ZX plane of AxisSystem36 | YZ plane of AxisSystem36], Start 0, End 304.8
  Line75 "H Rotation Axis": type PtDir, RefPoint {point type Coord, X 0, Y 0, Z 1015.8984 {= `External.Rotate Axis Offset`}, RefPoint vertex [YZ plane of AxisSystem36 | ZX plane of AxisSystem36 | XY plane of AxisSystem36], RefAxis AxisSystem36}, Direction edge [XY plane of AxisSystem36 | ZX plane of AxisSystem36], Start 0, End 304.8
  Point186 "Translate Point": (0 {= `External.X Translate`}, 0, 0 {= `External.Z Translate`}), relative to vertex [YZ plane of AxisSystem36 | ZX plane of AxisSystem36 | XY plane of AxisSystem36], in AxisSystem36
  Line76 "Trans X Axis": type PtDir, RefPoint Point186, Direction edge [XY plane of AxisSystem36 | ZX plane of AxisSystem36], Start 0, End 304.8
  Line77 "Trans ZAxis": type PtDir, RefPoint Point186, Direction edge [ZX plane of AxisSystem36 | YZ plane of AxisSystem36], Start 0, End 304.8
  Rotate25 "Rotate Horizontal Point": ToTransfor Point186, Axis Line75, Angle 0 {= `External.Open Angle`}
  Rotate26 "Rotate Horizontal Z Axis": ToTransfor Line77, Axis Line75, Angle 0 {= `External.Open Angle`}
  Rotate27 "Rotate Vertical Point": ToTransfor Point186, Axis Line74, Angle 0 {= `External.Open Angle`}
  Rotate28 "Rotate Vertical X Axis": ToTransfor Line76, Axis Line74, Angle 0 {= `External.Open Angle`}
  Line78 "X Direction": stored without definition
  Line79 "Z Direction": stored without definition
  Point187 "Origin": stored without definition
  Plane18: type Normal, Curve Line79, RefPoint Point187
  Line80 "Y Direction": type Angle, RefPoint Point187, Curve Line78, Support Plane18, Start 0, End 304.8, Angle 90
  AxisSystem38 "Window Open Axis": origin (14254.236, 8735.553, 152.4), X (0.3511, 0.9364, 0), Y (-0.9364, 0.3511, 0), Z (0, 0, 1)
Set67 "UDF Geometry"
  Point188 "B-L": (25.4 {= UdfFeature25.FrameThickness}, 0, 25.4 {= UdfFeature25.FrameThickness}), relative to vertex [YZ plane of UdfFeature25 | ZX plane of UdfFeature25 | XY plane of UdfFeature25], in 
  Point189 "B": (507.9492 {= `UdfFeature25.Panel Width` /2}, 0, 25.4 {= UdfFeature25.FrameThickness}), relative to vertex [YZ plane of UdfFeature25 | ZX plane of UdfFeature25 | XY plane of UdfFeature25], in 
  Point190 "B-R": (990.4984 {= `UdfFeature25.Panel Width` -UdfFeature25.FrameThickness}, 0, 25.4 {= UdfFeature25.FrameThickness}), relative to vertex [YZ plane of UdfFeature25 | ZX plane of UdfFeature25 | XY plane of UdfFeature25], in 
  Point191 "R": (990.4984 {= Point190.X}, 0, 1143 {= `UdfFeature25.Panel Height` /2}), relative to vertex [YZ plane of UdfFeature25 | ZX plane of UdfFeature25 | XY plane of UdfFeature25], in 
  Point192 "T-R": (990.4984 {= Point190.X}, 0, 2260.6 {= `UdfFeature25.Panel Height` -UdfFeature25.FrameThickness}), relative to vertex [YZ plane of UdfFeature25 | ZX plane of UdfFeature25 | XY plane of UdfFeature25], in 
  Point193 "T": (507.9492 {= Point189.X}, 0, 2260.6 {= Point192.Z}), relative to vertex [YZ plane of UdfFeature25 | ZX plane of UdfFeature25 | XY plane of UdfFeature25], in 
  Point194 "T-L": (25.4 {= Point188.X}, 0, 2260.6 {= Point192.Z}), relative to vertex [YZ plane of UdfFeature25 | ZX plane of UdfFeature25 | XY plane of UdfFeature25], in 
  Point195 "L": (25.4 {= Point188.X}, 0, 1143 {= Point191.Z}), relative to vertex [YZ plane of UdfFeature25 | ZX plane of UdfFeature25 | XY plane of UdfFeature25], in 
  Point196 "C": (507.9492 {= `UdfFeature25.Panel Width` /2}, 0, 1143 {= `UdfFeature25.Panel Height` /2}), relative to vertex [YZ plane of UdfFeature25 | ZX plane of UdfFeature25 | XY plane of UdfFeature25], in 
  Point197 "B2": (0, 0, 76.2), relative to Point189, in 
  Point198 "T2": (0, 0, -76.2), relative to Point193, in 
  Point199 "L2": (76.2, 0, 0), relative to Point195, in 
  Point200 "R2": (-76.2, 0, 0), relative to Point191, in 
  Point201 "L3": (-253.9746 {= -`UdfFeature25.Panel Width` /4}, 0, 0), relative to Point196, in 
  Point202 "R3": (253.9746 {= -Point201.X}, 0, 0), relative to Point196, in 
  Point203 "T3": (0, 0, 571.5 {= `UdfFeature25.Panel Height` /4}), relative to Point196, in 
  Point204 "B3": (0, 0, -571.5 {= - Point203.Z}), relative to Point196, in 
  LineCorner68 "Left": Elements (Point194; Point191; Point188)
  LineCorner69 "Right": Elements (Point192; Point195; Point190)
  LineCorner70 "Top": Elements (Point194; Point189; Point192)
  LineCorner71 "Bottom": Elements (Point188; Point193; Point190)
  Join31 "Left and Bottom": Elements (LineCorner68; LineCorner71)
  Join32 "Right and Bottom": Elements (LineCorner69; LineCorner71)
  LineCorner72 "Pivot H Top": Elements (Point199; Point195; Point193; Point191; Point200)
  LineCorner73 "Pivot H Bottom": Elements (Point195; Point189; Point191)
  Join33 "Pivot H": Elements (LineCorner72; LineCorner73)
  LineCorner74 "Pivot V Left": Elements (Point198; Point193; Point195; Point189; Point197)
  LineCorner75 "Pivot V Right": Elements (Point193; Point191; Point189)
  Join34 "Pivot V": Elements (LineCorner74; LineCorner75)
  Line81 "Sliding H": type PtPt, FirstPoint Point201, SecondPoint Point202
  Line82 "Sliding V": type PtPt, FirstPoint Point203, SecondPoint Point204
  Point205: (25.4 {= UdfFeature25.FrameThickness}, 0, 0), relative to Point188, in 
  Point206: (-25.4 {= -UdfFeature25.FrameThickness}, 0, 25.4 {= UdfFeature25.FrameThickness}), relative to Point190, in 
  Point207: (25.4 {= UdfFeature25.FrameThickness}, 0, -25.4 {= -UdfFeature25.FrameThickness}), relative to Point194, in 
  Point208: (-25.4 {= -UdfFeature25.FrameThickness}, 0, 0), relative to Point192, in 
  Point209: (0, 0, -25.4 {= -UdfFeature25.FrameThickness}), relative to Point192, in 
  Point210: (0, 0, 25.4 {= UdfFeature25.FrameThickness}), relative to Point188, in 
  LineCorner76 "Removable-1": Elements (Point194; Point208; Point206; Point210)
  LineCorner77 "Removable-2": Elements (Point207; Point209; Point190; Point205)
  Line83 "Removable-3": type PtPt, FirstPoint Point209, SecondPoint Point205
  Join35 "Removable": Elements (LineCorner76; LineCorner77; Line83)
  LineCorner78 "Fixed": Elements (Point194; Point192; Point190; Point188)
  DatumCurve7 "OperationSymbol"
Body35 "Opening Volume Body"
  GTCArcGeoOpnVolume8 "Opening Volume"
